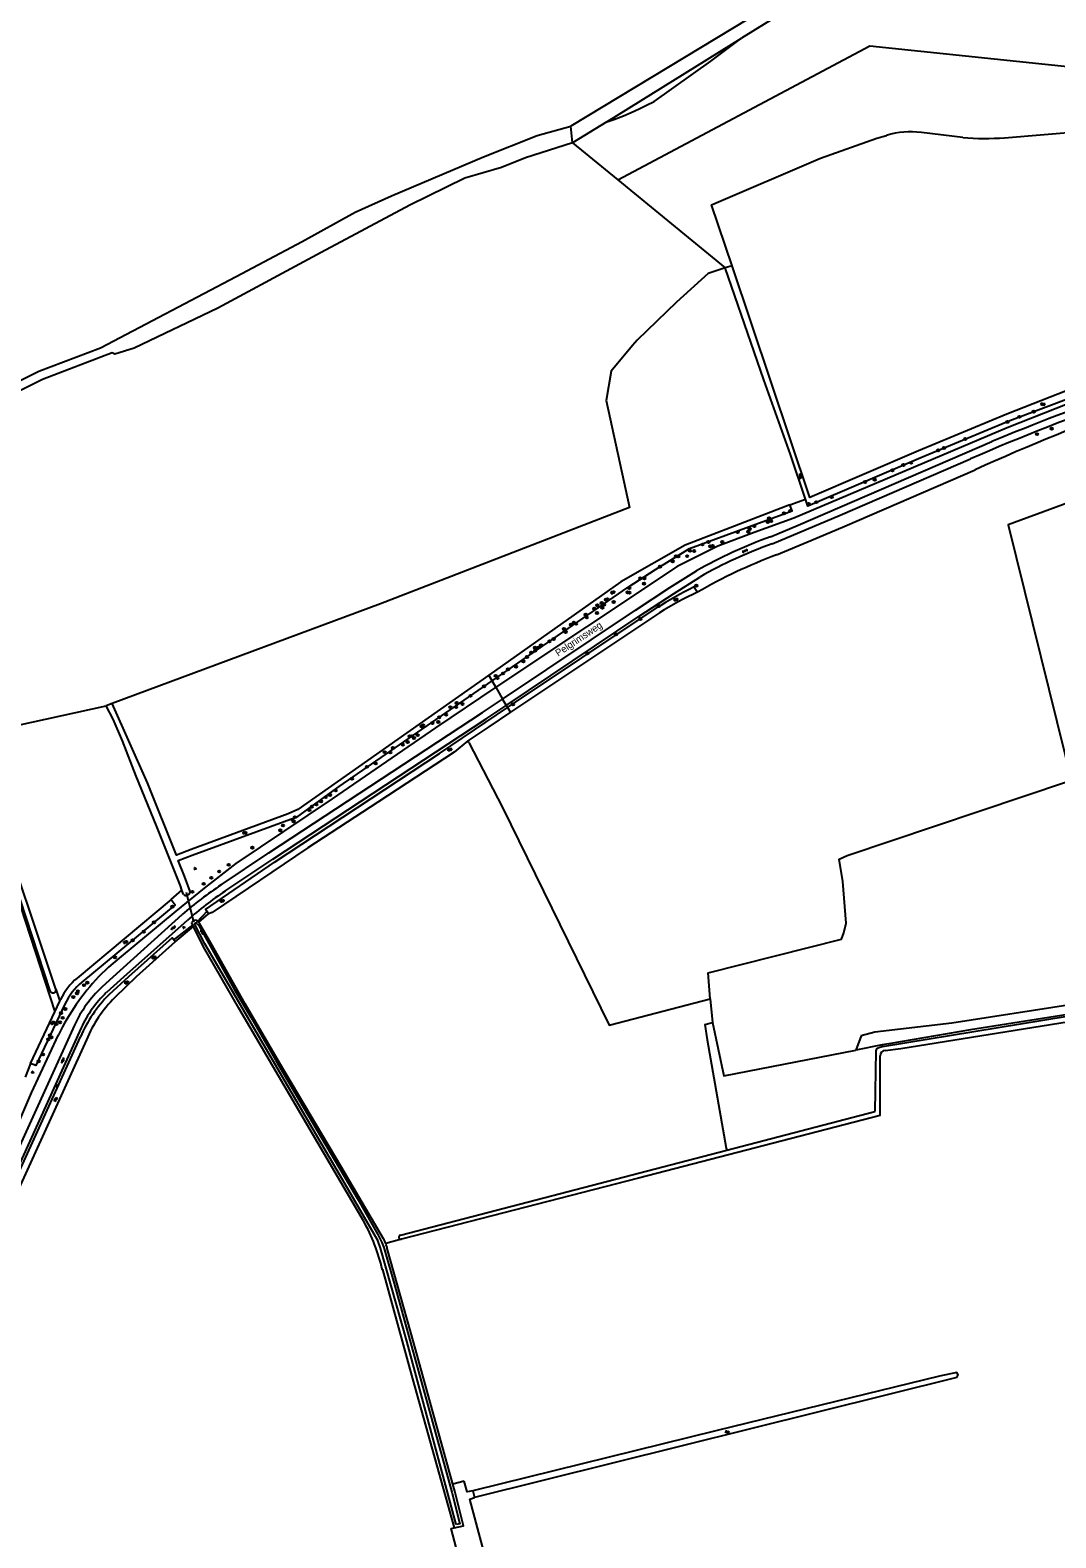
# Model space of a CAD drawing. Extents: x 134297 to 137000, y 403500 to 406000.
# Drawn here: x 135347 to 135711, y 404801 to 405336 of the extents above; entities that cross this region are included whole.
import ezdxf

# ---------------------------------------------------------------- set-up
doc = ezdxf.new("R2010")
doc.units = 0
for name, color, linetype in [('gg-anno-openbare ruimte label', 7, 'Continuous'), ('gg-knt-bronhoudergrens', 7, 'Continuous'), ('gg-knt-onverhard', 7, 'Continuous'), ('gg-knt-verharding', 7, 'Continuous'), ('gg-kntw-bovenkant insteek waterloop', 7, 'Continuous'), ('gg-kntw-waterlijn', 7, 'Continuous'), ('gg-kwrk-duiker nz buis', 7, 'Continuous'), ('gt-grn-groengrens', 7, 'Continuous'), ('gt-grn-weggrens', 7, 'Continuous'), ('gt-symb-boom', 7, 'Continuous'), ('gt-symb-gesloten verharding', 7, 'Continuous'), ('gt-symb-groenvak', 7, 'Continuous'), ('gt-symb-watersymbool', 7, 'Continuous'), ('gx-grn-maaiveld', 7, 'Continuous')]:
    doc.layers.add(name, color=color, linetype=linetype)

# ---------------------------------------------------------------- blocks, each defined once
blk = doc.blocks.new('gt0-BOOM')
at = {"layer": 'gt-symb-boom'}
for radius in [0.4, 0.2]:
    blk.add_circle((0, 0), radius, dxfattribs=at)
blk = doc.blocks.new('gt0-WA')
at = {"layer": 'gt-symb-watersymbool'}
for centre, start, end in [((-0.32, 0.02), 28.0725, 151.9275), ((0.43, 0.42), 208.0725, 331.9275), ((-0.32, -0.43), 28.0725, 151.9275), ((0.43, -0.03), 208.0725, 331.9275)]:
    blk.add_arc(centre, 0.425, start, end, dxfattribs=at)
blk = doc.blocks.new('gt0-GESVH1')
at = {"layer": 'gt-symb-gesloten verharding'}
for p, q in [((-0.99, -0.26), (0.01, 0.24)), ((0.01, -0.26), (-0.99, 0.24)), ((0.01, 0.24), (1.01, -0.26)), ((1.01, 0.24), (0.01, -0.26))]:
    blk.add_line(p, q, dxfattribs=at)
blk = doc.blocks.new('gt0-GRVAK')
at = {"layer": 'gt-symb-groenvak'}
for p, q in [((-0.11, 0.19), (-0.23, 0.24)), ((-0.18, 0.15), (0.09, 0.15)), ((-0.09, 0.21), (-0.16, 0.32)), ((-0.05, 0.21), (-0.05, 0.39)), ((0, 0.21), (0.06, 0.32)), ((0.01, 0.19), (0.13, 0.24)), ((0.26, -0.05), (0.2, 0.06)), ((0.3, -0.05), (0.3, 0.13)), ((0.35, -0.05), (0.41, 0.06)), ((-0.24, -0.23), (-0.36, -0.18)), ((-0.32, -0.26), (-0.05, -0.26)), ((-0.23, -0.21), (-0.29, -0.09)), ((-0.18, -0.2), (-0.18, -0.02)), ((-0.14, -0.21), (-0.07, -0.09)), ((-0.12, -0.23), (0, -0.18)), ((0.24, -0.07), (0.12, -0.02)), ((0.17, -0.11), (0.44, -0.11)), ((0.37, -0.07), (0.49, -0.02))]:
    blk.add_line(p, q, dxfattribs=at)

msp = doc.modelspace()

# ---------------------------------------------------------------- linework, layer by layer
at = {"layer": 'gg-knt-bronhoudergrens'}
for p, q in [((135693.03, 405298.09), (135721.15, 405300.36)), ((135396.87, 405027.56), (135400.71, 405030.78)), ((135355.98, 404995.66), (135357.39, 404991.46)), ((135588.36, 404992.28), (135589.25, 404983.86)), ((135586.5, 404983.14), (135589.25, 404983.86)), ((135649.58, 404975.84), (135640.14, 404974)), ((135478.69, 404906.88), (135473.16, 404905.36)), ((135501.05, 404820.93), (135496.98, 404819.8))]:
    msp.add_line(p, q, dxfattribs=at)
for points in [[(135803.88, 405182.77), (135800.12, 405199.53), (135694.29, 405160.59), (135717.36, 405067.27)], [(135328.12, 405078.68), (135325.76, 405085.72), (135373.76, 405096.28)], [(135502.64, 405083.3), (135514.65, 405060.21), (135552.55, 404982.86), (135588.36, 404992.28)], [(135588.36, 404992.28), (135587.69, 405001.52), (135635.11, 405013.39), (135635.86, 405015.65), (135636.71, 405019.16), (135635.61, 405033.91), (135634.3, 405041.9), (135637.09, 405043.14), (135715.35, 405069.46), (135716.38, 405066.9)], [(135884.96, 404975.82), (135883.67, 404976.71), (135882.01, 404979.17), (135857.88, 405046.96), (135855.18, 405055.29), (135853.35, 405056.8), (135851.61, 405057.75), (135849.78, 405057.35), (135847.24, 405056.64), (135832, 405043.46), (135799.22, 405017.43), (135789.69, 405009.89), (135783.11, 405006.79), (135776.28, 405003.78), (135765.72, 404999.73), (135755.72, 404996.71), (135734.13, 404992.66), (135717.07, 404990.28), (135674.28, 404983.61), (135646.9, 404980.36), (135642.06, 404979.09), (135640.14, 404974)], [(135880.44, 404973.32), (135876.02, 404985.91), (135858.05, 405035.74), (135851.68, 405053.42), (135832.82, 405039.31), (135795.26, 405010.18), (135780.87, 405000.6), (135771.57, 404997.29), (135765.88, 404995.55), (135760.94, 404994.34), (135755.82, 404993.24), (135750.25, 404992.28), (135723.78, 404987.98), (135680.91, 404981.28), (135651.89, 404976.29), (135649.58, 404975.84)], [(135586.5, 404983.14), (135587.4, 404977.63), (135594.12, 404939.18), (135594.3, 404938.48)], [(135589.25, 404983.86), (135593.22, 404964.87), (135640.14, 404974)], [(135504.05, 404817.48), (135502.1, 404817.12), (135501.05, 404820.93)], [(135528.54, 404729.26), (135526.97, 404734.31), (135524.65, 404733.59), (135503, 404814.58), (135504.7, 404815.1)], [(135498.71, 404795.16), (135496.42, 404804.07), (135497.44, 404804.3)]]:
    msp.add_lwpolyline(points, dxfattribs=at)
for centre, radius, start, end in [((135659.76, 405269.39), 30.78, 83.0981, 106.3725), ((135685.8, 405400.78), 102.95, 265.7417, 274.0272)]:
    msp.add_arc(centre, radius, start, end, dxfattribs=at)
at = {"layer": 'gg-knt-onverhard'}
for points in [[(135745.12, 405214.43), (135728.81, 405208.76), (135693.91, 405195.01), (135618.17, 405162.92), (135604.03, 405157.86), (135591.19, 405153), (135576.66, 405145.83), (135512.27, 405102.88)], [(135512.27, 405102.88), (135490.78, 405088.54), (135454.07, 405063.33), (135419.91, 405040.29), (135408.6, 405031.49), (135398.57, 405023.37), (135378.39, 405006.7), (135374.65, 405003.46), (135371.12, 405000)], [(135324.03, 404904.94), (135347.24, 404958.83), (135356.9, 404979.43)]]:
    msp.add_lwpolyline(points, dxfattribs=at)
msp.add_arc((135428.31, 404945.26), 79.16, 136.2551, 154.4303, dxfattribs=at)
at = {"layer": 'gg-knt-verharding'}
for p, q in [((135376.3, 405000), (135400.86, 405022.15)), ((135380.11, 405000), (135402.75, 405020.19)), ((135376.3, 405000), (135372.23, 404996.32)), ((135380.11, 405000), (135373.87, 404994.43)), ((135362.61, 404982.93), (135326.1, 404902.92)), ((135364.98, 404981.97), (135328.66, 404902))]:
    msp.add_line(p, q, dxfattribs=at)
for points in [[(135609.86, 405156.38), (135619.73, 405160.43), (135688.51, 405190.13)], [(135610.5, 405153.89), (135622.57, 405158.91), (135634.6, 405164.04), (135680.9, 405184.03)], [(135514.67, 405098.71), (135561.83, 405130.33), (135574.05, 405138.29), (135583.61, 405144.31)], [(135515.94, 405096.47), (135563.21, 405128.17), (135575.43, 405136.14), (135584.71, 405142.06)], [(135414.68, 405032.67), (135431.61, 405044.04), (135507.54, 405093.93), (135514.67, 405098.71)], [(135416.03, 405030.47), (135432.99, 405041.84), (135508.88, 405091.74), (135515.94, 405096.47)]]:
    msp.add_lwpolyline(points, dxfattribs=at)
for centre, radius, start, end in [((136030.42, 404374.26), 881.97, 109.49559, 113.34641), ((136021.65, 404391.9), 864.96, 109.33935, 112.65327), ((135670.64, 404989.61), 177.49, 110.025, 119.3618), ((135669.1, 404992.1), 172.07, 109.9119, 119.3676), ((135472.02, 404943.06), 106.39, 122.6182, 131.982), ((135483.21, 404929.97), 120.89, 123.7568, 131.7264), ((135401.36, 404965.24), 42.6, 133.1504, 155.4673), ((135401.23, 404965.5), 39.82, 133.4102, 155.5711)]:
    msp.add_arc(centre, radius, start, end, dxfattribs=at)
at = {"layer": 'gg-kntw-bovenkant insteek waterloop'}
for p, q in [((135622.25, 405169.75), (135616.93, 405185.59)), ((135582.73, 405138.51), (135583.96, 405136.72)), ((135516.44, 405095.67), (135569.25, 405130.95)), ((135570.37, 405129.37), (135517.43, 405094.01)), ((135375.91, 405097.1), (135373.76, 405096.28)), ((135355.98, 404995.66), (135328.12, 405078.68)), ((135401.23, 405029.24), (135400.71, 405030.78)), ((135396.87, 405027.56), (135363.52, 404999.62)), ((135404.83, 405017.92), (135404.14, 405019.3)), ((135355.57, 404987.59), (135357.39, 404991.46)), ((135357.39, 404991.46), (135357.63, 404991.97)), ((135346.96, 404969.29), (135355.57, 404987.59)), ((135647.27, 404973.77), (135646.92, 404952.18)), ((135648.83, 404950.85), (135648.83, 404971.95)), ((135594.3, 404938.48), (135646.92, 404952.18)), ((135478.33, 404908.27), (135594.3, 404938.48)), ((135676.01, 404857.72), (135504.7, 404815.1)), ((135504.05, 404817.48), (135504.7, 404815.1))]:
    msp.add_line(p, q, dxfattribs=at)
for points in [[(135616.93, 405185.59), (135607.46, 405212.13), (135593.8, 405251.82)], [(135737.94, 405213.7), (135694.86, 405197.53), (135663.22, 405184.41), (135623.08, 405167.27), (135622.25, 405169.75)], [(135616.76, 405167.67), (135579.59, 405153.37), (135556.72, 405140.39), (135509.73, 405107.25)], [(135510.96, 405105.13), (135559.3, 405138.44), (135569, 405144.69), (135581.04, 405152.19), (135617.5, 405165.62), (135616.76, 405167.67)], [(135509.73, 405107.25), (135441.93, 405059.44), (135438.45, 405057.94), (135403.98, 405045.31)], [(135404.42, 405043.24), (135441.91, 405057.02), (135456.62, 405067.67), (135510.96, 405105.13)], [(135400.71, 405030.78), (135400.17, 405032.4), (135391.73, 405053.74), (135384.5, 405071.33), (135379.6, 405083.88), (135376.29, 405091.51), (135373.76, 405096.28)], [(135403.98, 405045.31), (135398.83, 405043.23), (135388.45, 405069.01), (135375.91, 405097.1)], [(135410.18, 405022.41), (135409.06, 405023.99), (135433.6, 405040.81), (135492.3, 405079.4), (135508.67, 405090.47), (135516.44, 405095.67)], [(135517.43, 405094.01), (135509.78, 405088.9), (135502.29, 405083.83)], [(135502.29, 405083.83), (135497.49, 405079.88), (135470.28, 405062.04), (135445.49, 405045.91), (135411.42, 405022.93), (135410.18, 405022.41)], [(135403.68, 405030.31), (135401.68, 405035.8), (135399.4, 405041.35), (135404.42, 405043.24)], [(135396.87, 405027.56), (135398.33, 405025.68), (135365.21, 404998.16)], [(135465.25, 404913.37), (135420.92, 404988.96), (135408.45, 405010.67), (135404.83, 405017.92)], [(135472.32, 404906.97), (135457.2, 404932.85), (135435.43, 404969.56), (135423.18, 404990.47), (135410.96, 405012.12), (135407.02, 405019.07), (135406.86, 405019.28), (135406.69, 405019.48)], [(135398.37, 405012.48), (135397.23, 405013.85), (135381.76, 405000), (135374.8, 404993.7)], [(135398.37, 405012.48), (135384.42, 405000), (135376.87, 404992.67)], [(135649.68, 404975.25), (135756.37, 404992.86), (135764.97, 404994.87)], [(135359.13, 404990.33), (135348.82, 404968.51), (135346.96, 404969.29)], [(135650.6, 404973.93), (135656.17, 404974.57), (135721.84, 404985.18)], [(135323.77, 404890.03), (135338.22, 404920.42), (135364.73, 404978.76)], [(135366.79, 404977.72), (135340.28, 404919.38), (135325.84, 404888.99)], [(135648.83, 404950.85), (135562.92, 404928.5), (135478.69, 404906.88)], [(135496.98, 404819.8), (135483.13, 404869.9), (135473.69, 404903.54)], [(135471.95, 404896.04), (135482.7, 404857.31), (135497.44, 404804.3)], [(135676.01, 404857.72), (135676.53, 404858.68), (135676.01, 404859.53), (135669.88, 404858.24), (135590.88, 404838.91), (135504.05, 404817.48)], [(135497.44, 404804.3), (135500.72, 404805.05), (135497.64, 404817.41), (135496.98, 404819.8)]]:
    msp.add_lwpolyline(points, dxfattribs=at)
for centre, radius, start, end in [((135639.34, 405021.92), 129.61, 115.9, 122.7364), ((135638.69, 405019.21), 129.63, 114.9725, 121.8063), ((135402.17, 405030.43), 1.51, 231.5184, 355.5932), ((135405.94, 405018.01), 2.21, 98.955, 144.5015), ((135404.59, 405017.46), 2.91, 43.9208, 69.8661), ((135377.65, 404982.65), 22.09, 129.7907, 155.0331), ((135379.93, 404980.46), 23.02, 129.7542, 154.6367), ((135407.29, 404960.93), 46.14, 134.7475, 157.2674), ((135409.35, 404959.89), 46.14, 134.7475, 157.2674), ((135650.68, 404970.04), 5.31, 100.8257, 124.2586), ((135648.04, 404973.74), 0.769, 117.2103, 178.3753), ((135650.83, 404971.95), 2, 96.5112, 180.0003), ((135404.56, 404879.97), 69.27, 13.4135, 28.8262), ((135464.34, 404901.79), 9.51, 27.5529, 33.0056), ((135464.12, 404901.68), 9.76, 22.1375, 27.5347), ((135464.23, 404901.75), 9.63, 10.7142, 22.0308), ((135478.54, 404907.58), 0.718, 106.8064, 282.4085)]:
    msp.add_arc(centre, radius, start, end, dxfattribs=at)
at = {"layer": 'gg-kntw-waterlijn'}
msp.add_lwpolyline([(135498.21, 404805.58), (135480.66, 404870.66), (135471.29, 404903.71), (135470.3, 404906.38), (135458.73, 404926.42), (135447.35, 404945.8), (135408.88, 405011.75), (135405.18, 405018.85), (135405.69, 405019.25), (135406.71, 405018.25), (135419.3, 404995.69), (135425.17, 404985.75), (135434.14, 404970.31), (135446.88, 404948.61), (135463.36, 404920.83), (135470.3, 404908.57), (135471.8, 404905.74), (135472.48, 404903.86), (135476.43, 404890.32), (135496.62, 404816.96), (135499.5, 404805.74), (135498.21, 404805.58)], dxfattribs=at)
at = {"layer": 'gg-kwrk-duiker nz buis'}
for p, q in [((135404.97, 405019.45), (135402.37, 405030.04)), ((135409.8, 405023.51), (135405.77, 405019.19)), ((135404.62, 405018.49), (135397.65, 405013.09))]:
    msp.add_line(p, q, dxfattribs=at)
at = {"layer": 'gt-grn-groengrens'}
for p, q in [((135616.76, 405167.67), (135622.25, 405169.75)), ((135510.96, 405105.13), (135509.73, 405107.25)), ((135512.27, 405102.88), (135510.96, 405105.13)), ((135512.27, 405102.88), (135514.67, 405098.71)), ((135516.44, 405095.67), (135515.94, 405096.47)), ((135516.44, 405095.67), (135517.43, 405094.01)), ((135502.64, 405083.3), (135502.29, 405083.83)), ((135398.37, 405012.48), (135404.83, 405017.92)), ((135406.69, 405019.48), (135410.18, 405022.41)), ((135649.68, 404975.25), (135649.58, 404975.84)), ((135346.96, 404969.29), (135345.02, 404964.39))]:
    msp.add_line(p, q, dxfattribs=at)
msp.add_lwpolyline([(135611.95, 405149.89), (135624.22, 405155), (135636.28, 405160.14), (135682.59, 405180.13)], dxfattribs=at)
for centre, radius, start, end in [((135970.82, 404549.69), 693.2, 109.40112, 114.56999), ((135677.54, 404974.17), 187.56, 110.4694, 119.9281)]:
    msp.add_arc(centre, radius, start, end, dxfattribs=at)
at = {"layer": 'gt-grn-weggrens'}
msp.add_line((135514.67, 405098.71), (135515.94, 405096.47), dxfattribs=at)
at = {"layer": 'gx-grn-maaiveld'}
for p, q in [((135638.74, 405357.77), (135599.49, 405333.42)), ((135551.7, 405303.78), (135599.49, 405333.42)), ((135539.52, 405296.22), (135538.87, 405302.16)), ((135551.7, 405303.78), (135539.52, 405296.22)), ((135539.52, 405296.22), (135555.59, 405283.07)), ((135678.15, 405298.11), (135663.46, 405299.94)), ((135555.59, 405283.07), (135593.8, 405251.82)), ((135596.18, 405252.61), (135593.8, 405251.82)), ((135326.07, 405077.88), (135355.57, 404987.59)), ((135326.53, 405078.06), (135353.83, 404995.12))]:
    msp.add_line(p, q, dxfattribs=at)
for points in [[(135638.74, 405357.77), (135636.71, 405361.44), (135538.87, 405302.16)], [(135551.7, 405303.78), (135554.24, 405304.59), (135557.61, 405305.89), (135560.39, 405307.05), (135563.13, 405308.29), (135565.83, 405309.59), (135568.51, 405310.97), (135588.64, 405325.23), (135599.49, 405333.42)], [(135555.59, 405283.07), (135645.15, 405330.75), (135741.41, 405320.69), (135745.35, 405292.86), (135773.36, 405275.89), (135804.01, 405282.17), (135808.41, 405328.31)], [(135330.59, 405205.58), (135349.93, 405215.19), (135371.79, 405223.5), (135420.04, 405248.79), (135443.48, 405261.27), (135462.24, 405271.68), (135475.19, 405277.42), (135507.86, 405291.32), (135526.95, 405298.87), (135538.87, 405302.16)], [(135539.52, 405296.22), (135522.76, 405290.92), (135514.26, 405287.47), (135501.21, 405283.74), (135481.69, 405274.12), (135450.19, 405257.26), (135413.54, 405237.58), (135383.8, 405223.31), (135376.88, 405221.22), (135375.91, 405221.65), (135351.21, 405212.26), (135331.82, 405202.62)], [(135596.18, 405252.61), (135588.9, 405274.27), (135627.6, 405290.77), (135647.69, 405297.96), (135651.08, 405298.92)], [(135593.8, 405251.82), (135587.73, 405249.87), (135576.43, 405239.72), (135562.43, 405226.14), (135560.85, 405224.24)], [(135736.65, 405216.68), (135693.81, 405199.88), (135662.38, 405186.83), (135623.84, 405170.35), (135596.18, 405252.61)], [(135560.85, 405224.24), (135553.28, 405215.13), (135551.42, 405204.7), (135559.77, 405166.75), (135471.24, 405132.59), (135375.91, 405097.1)], [(135353.83, 404995.12), (135353.9, 404994.95), (135354, 404994.78), (135354.13, 404994.64), (135354.28, 404994.52), (135354.45, 404994.43), (135354.73, 404994.35), (135355.02, 404994.34), (135355.3, 404994.41), (135355.55, 404994.55), (135355.76, 404994.75), (135355.9, 404995), (135355.98, 404995.28), (135355.99, 404995.47), (135355.98, 404995.66)]]:
    msp.add_lwpolyline(points, dxfattribs=at)

# ---------------------------------------------------------------- block references
at = {"layer": 'gt-symb-boom'}
for p in [(135703.4, 405200.8), (135694.04, 405197.16), (135698.3, 405198.95), (135709.78, 405194.74), (135679.02, 405191.09), (135704.55, 405192.79), (135669.43, 405187.04), (135671.49, 405187.9), (135653.14, 405179.95), (135657.06, 405181.8), (135659.83, 405182.6), (135643.46, 405175.78), (135646.88, 405176.62), (135623.4, 405168.06), (135626.13, 405168.64), (135631.58, 405170.48), (135609.34, 405162.94), (135610.05, 405161.97), (135614.62, 405164.66), (135616.83, 405165.56), (135598.17, 405158.02), (135601.94, 405158.13), (135602.44, 405159.1), (135604.15, 405160.12), (135608.89, 405161.64), (135581.26, 405151.35), (135582.73, 405151.3), (135585.69, 405153.6), (135587.78, 405154.5), (135588.46, 405152.91), (135589.29, 405153.14), (135592.71, 405154.53), (135575.12, 405147.61), (135576.26, 405149.39), (135577.1, 405149.36), (135580.24, 405149.47), (135563.55, 405141.64), (135565.03, 405141.57), (135570.58, 405145.73), (135559.03, 405136.58), (135559.67, 405138.09), (135559.74, 405136.52), (135564.94, 405139.73), (135583.49, 405138.94), (135547.23, 405130.86), (135548.33, 405131.97), (135549.88, 405132.83), (135550.11, 405131.16), (135550.69, 405132.2), (135551.43, 405134.05), (135551.94, 405134.18), (135554.14, 405133.18), (135570.15, 405131.74), (135538.99, 405125.15), (135539.98, 405125.81), (135540.81, 405125.43), (135544.22, 405128.72), (135544.59, 405127.67), (135548.21, 405129.28), (135563.6, 405127.18), (135531.34, 405119.19), (135532.83, 405120.04), (135536.46, 405123.59), (135537.07, 405122.5), (135554.94, 405121.7), (135523.32, 405113.66), (135524.86, 405115.22), (135526.22, 405116.97), (135526.24, 405115.89), (135527.39, 405116.92), (135528.33, 405117.83), (135544.78, 405114.94), (135516.57, 405109.29), (135519.44, 405110.19), (135522.06, 405112.15), (135508.06, 405103.2), (135512.23, 405106.96), (135512.84, 405106.21), (135514.77, 405107.79), (135503.25, 405099.85), (135492.14, 405092.26), (135494.61, 405093.12), (135496.07, 405095.82), (135498.18, 405095.91), (135498.37, 405097.35), (135500.43, 405096.92), (135518.36, 405096.8), (135485.89, 405088.99), (135486.43, 405089.35), (135489.71, 405090.2), (135491.81, 405090.59), (135479.22, 405082.53), (135480.93, 405083.46), (135481.66, 405085.44), (135482.37, 405085.54), (135483.15, 405084.87), (135484.5, 405085.89), (135472.78, 405079.85), (135474.74, 405079.73), (135475.71, 405081.3), (135466.44, 405074.64), (135469.58, 405075.81), (135455.42, 405066.24), (135461.12, 405070.45), (135446.88, 405060.51), (135448.49, 405061.27), (135450.17, 405062.36), (135451.84, 405063.86), (135453.35, 405064.59), (135439.99, 405055.94), (135440.42, 405055.26), (135440.86, 405056.77), (135445.96, 405059.32), (135435.65, 405052.11), (135436.68, 405053.8), (135425.75, 405045.91), (135417.36, 405039.82), (135411.22, 405035.21), (135413.95, 405037.45), (135404.47, 405030.25), (135408.48, 405033.07), (135397.32, 405025.01), (135390.81, 405019.38), (135383.21, 405012.98), (135387.18, 405016.1), (135376.99, 405007), (135365.92, 404997.09), (135367.11, 404997.94), (135362.18, 404992.84), (135363.46, 404994.19), (135363.75, 404994.93), (135357.77, 404987.23), (135358.36, 404985.48), (135359.28, 404988.59), (135356.08, 404983.3), (135357.45, 404983.9), (135353.3, 404977.83), (135353.81, 404979.29), (135354.33, 404978.57), (135349.8, 404970), (135351.39, 404972.45)]:
    msp.add_blockref('gt0-BOOM', p, dxfattribs=at)
at = {"layer": 'gt-symb-gesloten verharding'}
for p, rotation in [((135600.78, 405151.33), 24.334874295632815), ((135397.64, 405017.45), 40.29689620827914), ((135358.37, 404970.34), 64.3321248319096)]:
    msp.add_blockref('gt0-GESVH1', p, dxfattribs=dict(at, rotation=rotation))
at = {"layer": 'gt-symb-groenvak'}
for p in [(135405.42, 405038.55), (135401.43, 405017.63), (135347.68, 404966.16), (135356.22, 404961.49)]:
    msp.add_blockref('gt0-GRVAK', p, dxfattribs=at)
at = {"layer": 'gt-symb-watersymbool'}
for p, rotation in [((135706.61, 405203.4), 24.462926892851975), ((135620.44, 405177.9), -61.17916405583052), ((135553.77, 405136.56), 46.62038199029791), ((135576.21, 405134), 43.01389341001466), ((135495.91, 405080.69), 43.01389341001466), ((135423.06, 405051.17), 30.541098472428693), ((135415.02, 405026.95), 43.01389341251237), ((135380.65, 405012.36), 49.29925519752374), ((135407.96, 405015.93), 143.98947459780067), ((135390.73, 405006.85), 54.975126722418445), ((135381.05, 404998.02), 53.98947459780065), ((135354.8, 404983.65), 64.97272120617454), ((135355.87, 404956.45), 73.97589034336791), ((135594.42, 404838.35), 13.952823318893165)]:
    msp.add_blockref('gt0-WA', p, dxfattribs=dict(at, rotation=rotation))

# ---------------------------------------------------------------- texts
at = {"layer": 'gg-anno-openbare ruimte label'}
msp.add_text('Pelgrimsweg', height=2.5, rotation=33.7, dxfattribs=at).set_placement((135534.42, 405113.74))

doc.saveas('drawing.dxf')
